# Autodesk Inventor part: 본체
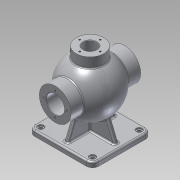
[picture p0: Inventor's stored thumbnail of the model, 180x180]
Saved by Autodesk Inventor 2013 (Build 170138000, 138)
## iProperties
Created: 2018-06
Part Number: 본체
Material: 알루미늄 6061
Document SubType Name: Modeling
Designer: Administrator
Density: 2.71 g/cm^3
Mass: 1509.81 g
Surface Area: 1154.15 cm^2
Volume: 557.126 cm^3
Author: Administrator
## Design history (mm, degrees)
sketch "스케치1"
  geometry: L1 (0, 53)-(0, -53); A1 r 53 centre (0, 0) between (0, -53) and (0, 53); A2 r 43 centre (0, 0) between (0, -43) and (0, 43); 1 further point
  constraints: 4 point on circle, 2 centre point, 2 coincident, 2 end point, 2 point on line, 1 midpoint, 1 vertical
  dimensions: "d0" = 53 radius of A1; "d1" = 43 radius of A2
revolve "회전1" sketch "스케치1" stored, may be unused: angle "d2" = 90 deg
node "작업 평면1"
sketch "스케치2"
  geometry: C1 r 31 at (0, 0); 1 further point
  constraints: 1 centre point, 1 coincident
  dimensions: "d4" = 62 diameter of C1
extrude "돌출1" join sketch "스케치2" stored distance "d5" = 10; taper "d6" = 0 deg
hole "구멍1" diameter "d9" = 35; stored, may be unused: countersink angle "d13" = 90 deg, drill point angle "d15" = 118 deg; dims "d7" = 10, "d8" = 10, "d10" = 6, "d11" = 4, "d12" = 2, "d14" = 8
node "작업 평면2"
sketch "스케치3"
  geometry: C1 r 27 at (0, 0); 1 further point
  constraints: 1 centre point, 1 coincident
  dimensions: "d17" = 54 diameter of C1
extrude "돌출2" join sketch "스케치3" stored distance "d18" = 10; taper "d19" = 0 deg
hole "구멍2" diameter "d22" = 26; stored, may be unused: countersink angle "d26" = 90 deg, drill point angle "d28" = 118 deg; dims "d23" = 6, "d24" = 4, "d25" = 2, "d27" = 8, "d48" = 10, "d49" = 10
node "작업 평면3"
sketch "스케치4"
  geometry: L1 (-62.5, -57.5)-(62.5, -57.5); L2 (62.5, -57.5)-(62.5, 57.5); L3 (62.5, 57.5)-(-62.5, 57.5); L4 (-62.5, 57.5)-(-62.5, -57.5); L5 (-62.5, -57.5)-(62.5, 57.5); L6 (62.5, -57.5)-(-62.5, 57.5); 1 further point
  constraints: 12 end point, 2 midpoint, 2 parallel, 1 horizontal, 1 perpendicular
  dimensions: "d30" = 125 distance of L2.end L3.end; "d32" = 115 distance of L1.end L2.end
extrude "돌출3" join sketch "스케치4" distance "d33" = 10; taper "d34" = 0 deg
fillet "모깎기1" dims "d35" = 12
sketch "스케치5"
  geometry: A1 r 12 centre (-50.5, 45.5) between (-50.5, 57.5) and (-62.5, 45.5) reference; A2 r 12 centre (-50.5, -45.5) between (-62.5, -45.5) and (-50.5, -57.5) reference; A3 r 12 centre (50.5, -45.5) between (50.5, -57.5) and (62.5, -45.5) reference; A4 r 12 centre (50.5, 45.5) between (62.5, 45.5) and (50.5, 57.5) reference; 5 further points
  constraints: 4 coincident
hole "구멍3" sketch "스케치5" at (-50.5, 45.5), (-50.5, -45.5), (50.5, -45.5), (50.5, 45.5) diameter "d36" = 8; stored, may be unused: countersink angle "d40" = 90 deg, drill point angle "d42" = 118 deg; dims "d37" = 6, "d38" = 12, "d39" = 3, "d41" = 8
sketch "스케치9"
  geometry: L1 (50.5, 57.5)-(-50.5, 57.5) reference; L2 (-4, -47.5)-(4, -47.5); L3 (4, -47.5)-(4, 47.5); L4 (4, 47.5)-(-4, 47.5); L5 (-4, 47.5)-(-4, -47.5); L6 (-4, -47.5)-(4, 47.5); L7 (4, -47.5)-(-4, 47.5); 1 further point
  constraints: 12 end point, 2 midpoint, 2 parallel, 1 horizontal, 1 perpendicular
  dimensions: "d52" = 8 distance of L3.end L4.end; "d54" = 10 distance between parallel lines of L1 L4
extrude "돌출4" join sketch "스케치9" stored distance "d55" = 10; taper "d56" = 0 deg
feature "면 기울기1" dims angle "d57" = 22 deg
feature "면 기울기2" dims angle "d58" = 22 deg
sketch "스케치10"
  geometry: L1 (62.5, -45.5)-(62.5, 45.5) reference; L2 (-52.5, -4)-(52.5, -4); L3 (52.5, -4)-(52.5, 4); L4 (52.5, 4)-(-52.5, 4); L5 (-52.5, 4)-(-52.5, -4); L6 (-52.5, -4)-(52.5, 4); L7 (52.5, -4)-(-52.5, 4); 1 further point
  constraints: 12 end point, 2 midpoint, 2 parallel, 1 horizontal, 1 perpendicular
  dimensions: "d59" = 8 distance of L2.end L3.end; "d61" = 10 distance between parallel lines of L1 L3
extrude "돌출5" join sketch "스케치10" stored distance "d62" = 10; taper "d63" = 0 deg
feature "면 기울기3" dims angle "d64" = 22 deg
feature "면 기울기4" dims angle "d65" = 22 deg
sketch "스케치11"
  geometry: C1 r 17.5 at (0, 0) reference; 1 further point
  constraints: 1 vertical alignment
  dimensions: "d66" = 22.5 distance of C1.centre point (0, 22.5)
hole "구멍4" sketch "스케치11" at (0, 22.5) diameter "d67" = 3.242; stored, may be unused: countersink angle "d71" = 90 deg, drill point angle "d73" = 118 deg; dims "d68" = 12, "d69" = 12, "d70" = 3, "d72" = 15
sketch "스케치12"
  geometry: C1 r 17.5 at (0, 0) reference; 1 further point
  constraints: 1 vertical alignment
  dimensions: "d77" = 24 distance of C1.centre point (0, -24)
hole "구멍5" sketch "스케치12" at (0, -24) diameter "d78" = 3.242; stored, may be unused: countersink angle "d82" = 90 deg, drill point angle "d84" = 118 deg; dims "d79" = 16, "d80" = 12, "d81" = 3, "d83" = 19
sketch "스케치13"
  geometry: C1 r 13 at (0, 0) reference; 1 further point
  constraints: 1 vertical alignment
  dimensions: "d88" = 20 distance of C1.centre point (0, 20)
hole "구멍6" sketch "스케치13" at (0, 20) diameter "d89" = 3.242; stored, may be unused: countersink angle "d93" = 90 deg, drill point angle "d95" = 118 deg; dims "d90" = 9, "d91" = 12, "d92" = 3, "d94" = 11
sketch "스케치14"
  geometry: L1 (50.25, 18.5)-(52, 18.5); L2 (52, 18.5)-(52, 0); L3 (52, 0)-(50.25, 0); L4 (50.25, 0)-(50.25, 18.5); L5 (68, 17.5)-(68, -17.5) reference; 1 further point
  constraints: 8 end point, 2 parallel, 1 horizontal, 1 perpendicular, 1 point on line
  dimensions: "d99" = 1.75 distance of L1.start L1.end; "d101" = 37 diameter of L1 L3; "d102" = 16 distance between parallel lines of L5 L2
revolve "회전2" sketch "스케치14" stored, may be unused: angle "d103" = 90 deg
fillet "모깎기2" dims "d104" = 1
fillet "모깎기3" dims "d105" = 3
fillet "모깎기4" dims "d106" = 3
node "작업 평면4"
sketch "스케치15"
  geometry: L1 (-27, 65)-(27, 65) reference; 2 further points
  constraints: 1 vertical alignment, 1 other
  dimensions: "d108" = 10 distance from line of L1 point (0, 55)
feature "엠보싱1" sketch "스케치15" dims "d17" = 54, "d109" = 0.5, "d110" = 0
node "솔리드1"
mirror "대칭1"
pattern_circular "원형 패턴1" dims angle "d75" = 360 deg
pattern_circular "원형 패턴2" dims angle "d86" = 360 deg
pattern_circular "원형 패턴3" dims angle "d97" = 360 deg
other parameters: "d3" = -68, "d16" = 65, "d29" = -85, "d107" = -27
